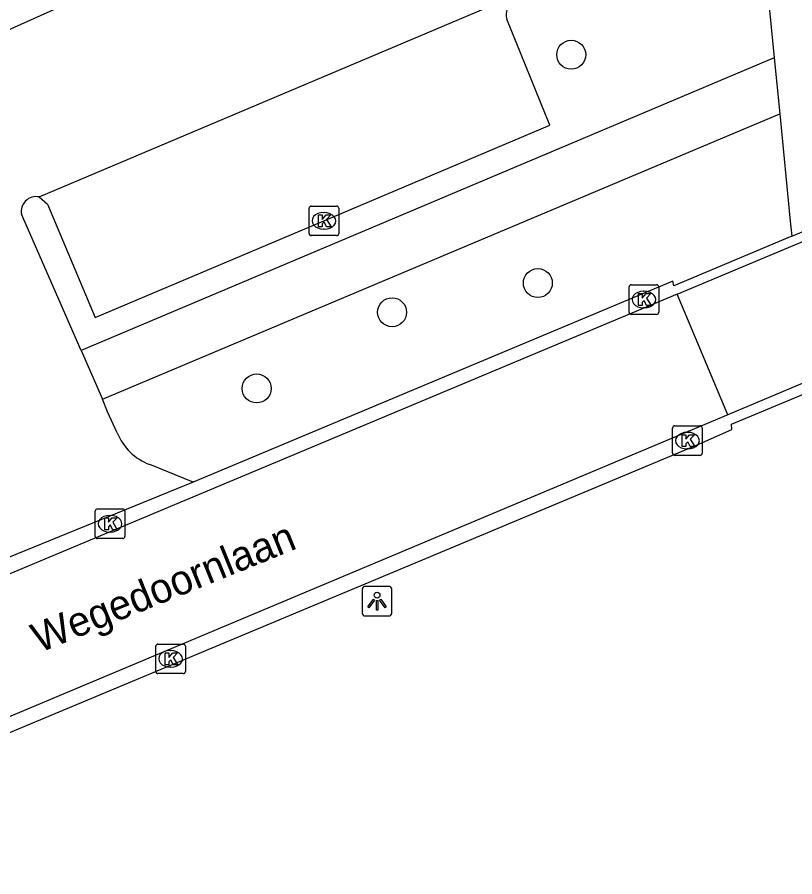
# Model space of a CAD drawing. Extents: x 162675 to 163482, y 379761 to 381227.
# Drawn here: x 163060.17 to 163086.44, y 380790.54 to 380819.57 of the extents above; entities that cross this region are included whole.
import ezdxf

# ---------------------------------------------------------------- set-up
doc = ezdxf.new("R2010")
doc.units = 0
for name, color, linetype in [('IMGEO_Boom', 7, 'Continuous'), ('IMGEO_Kolk', 7, 'Continuous'), ('IMGEO_Lichtpunt', 7, 'Continuous'), ('IMGEO_Openbare_ruimte_label', 7, 'Continuous'), ('IMGEO_Parkeervlak_open', 7, 'Continuous'), ('IMGEO_Rijbaan_lokaal_gesloten', 7, 'Continuous'), ('IMGEO_Rijbaan_lokaal_open', 7, 'Continuous'), ('IMGEO_Voetpad_open', 7, 'Continuous')]:
    doc.layers.add(name, color=color, linetype=linetype)

msp = doc.modelspace()

# ---------------------------------------------------------------- linework, layer by layer
at = {"layer": 'IMGEO_Boom'}
for centre in [(163078.885, 380818.302), (163077.757, 380810.591), (163072.834, 380809.603), (163068.26, 380807.03)]:
    msp.add_circle(centre, 0.489, dxfattribs=at)
at = {"layer": 'IMGEO_Kolk'}
for p, q in [((163070.105, 380813.191), (163070.957, 380813.191)), ((163070.03, 380812.265), (163070.03, 380813.117)), ((163070.518, 380812.971), (163070.543, 380812.971)), ((163071.031, 380813.117), (163071.031, 380812.265)), ((163070.541, 380812.411), (163070.516, 380812.411)), ((163070.957, 380812.191), (163070.105, 380812.191)), ((163080.839, 380809.607), (163080.839, 380810.459)), ((163080.914, 380810.533), (163081.766, 380810.533)), ((163081.327, 380810.313), (163081.352, 380810.313)), ((163081.84, 380810.459), (163081.84, 380809.607)), ((163081.35, 380809.753), (163081.325, 380809.753)), ((163081.766, 380809.533), (163080.914, 380809.533)), ((163082.31, 380804.842), (163082.31, 380805.694)), ((163082.385, 380805.768), (163083.237, 380805.768)), ((163083.311, 380805.694), (163083.311, 380804.842)), ((163082.798, 380805.548), (163082.823, 380805.548)), ((163082.821, 380804.988), (163082.796, 380804.988)), ((163083.237, 380804.768), (163082.385, 380804.768)), ((163062.808, 380802.033), (163062.808, 380802.885)), ((163062.883, 380802.959), (163063.735, 380802.959)), ((163063.296, 380802.739), (163063.321, 380802.739)), ((163063.809, 380802.885), (163063.809, 380802.033)), ((163063.319, 380802.179), (163063.294, 380802.179)), ((163063.735, 380801.959), (163062.883, 380801.959)), ((163064.925, 380798.397), (163065.777, 380798.397)), ((163064.85, 380797.471), (163064.85, 380798.323)), ((163065.338, 380798.177), (163065.363, 380798.177)), ((163065.851, 380798.323), (163065.851, 380797.471)), ((163065.361, 380797.617), (163065.336, 380797.617)), ((163065.777, 380797.397), (163064.925, 380797.397))]:
    msp.add_line(p, q, dxfattribs=at)
for points in [[(163070.105, 380813.191), (163070.957, 380813.191)], [(163070.03, 380812.265), (163070.03, 380813.117)], [(163071.031, 380813.117), (163071.031, 380812.265)], [(163070.351, 380812.891), (163070.474, 380812.891), (163070.474, 380812.74), (163070.604, 380812.891), (163070.768, 380812.891), (163070.622, 380812.74), (163070.775, 380812.491), (163070.623, 380812.491), (163070.538, 380812.655), (163070.474, 380812.588), (163070.474, 380812.491), (163070.351, 380812.491), (163070.351, 380812.891)], [(163070.957, 380812.191), (163070.105, 380812.191)], [(163080.839, 380809.607), (163080.839, 380810.459)], [(163080.914, 380810.533), (163081.766, 380810.533)], [(163081.84, 380810.459), (163081.84, 380809.607)], [(163081.16, 380810.233), (163081.283, 380810.233), (163081.283, 380810.082), (163081.413, 380810.233), (163081.577, 380810.233), (163081.431, 380810.082), (163081.584, 380809.833), (163081.432, 380809.833), (163081.347, 380809.997), (163081.283, 380809.93), (163081.283, 380809.833), (163081.16, 380809.833), (163081.16, 380810.233)], [(163081.766, 380809.533), (163080.914, 380809.533)], [(163082.31, 380804.842), (163082.31, 380805.694)], [(163082.385, 380805.768), (163083.237, 380805.768)], [(163083.311, 380805.694), (163083.311, 380804.842)], [(163082.631, 380805.468), (163082.754, 380805.468), (163082.754, 380805.317), (163082.884, 380805.468), (163083.048, 380805.468), (163082.902, 380805.317), (163083.055, 380805.068), (163082.903, 380805.068), (163082.818, 380805.232), (163082.754, 380805.165), (163082.754, 380805.068), (163082.631, 380805.068), (163082.631, 380805.468)], [(163083.237, 380804.768), (163082.385, 380804.768)], [(163062.808, 380802.033), (163062.808, 380802.885)], [(163062.883, 380802.959), (163063.735, 380802.959)], [(163063.809, 380802.885), (163063.809, 380802.033)], [(163063.129, 380802.659), (163063.252, 380802.659), (163063.252, 380802.508), (163063.382, 380802.659), (163063.546, 380802.659), (163063.4, 380802.508), (163063.553, 380802.259), (163063.401, 380802.259), (163063.316, 380802.423), (163063.252, 380802.356), (163063.252, 380802.259), (163063.129, 380802.259), (163063.129, 380802.659)], [(163063.735, 380801.959), (163062.883, 380801.959)], [(163064.925, 380798.397), (163065.777, 380798.397)], [(163064.85, 380797.471), (163064.85, 380798.323)], [(163065.171, 380798.097), (163065.294, 380798.097), (163065.294, 380797.946), (163065.424, 380798.097), (163065.588, 380798.097), (163065.442, 380797.946), (163065.595, 380797.697), (163065.443, 380797.697), (163065.358, 380797.861), (163065.294, 380797.794), (163065.294, 380797.697), (163065.171, 380797.697), (163065.171, 380798.097)], [(163065.851, 380798.323), (163065.851, 380797.471)], [(163065.777, 380797.397), (163064.925, 380797.397)]]:
    msp.add_lwpolyline(points, dxfattribs=at)
for centre, start, end in [((163070.107, 380813.115), 91.552, 178.448), ((163070.107, 380813.115), 91.552, 178.448), ((163070.955, 380813.115), 1.552, 88.448), ((163070.955, 380813.115), 1.552, 88.448), ((163070.107, 380812.267), 181.552, 268.448), ((163070.107, 380812.267), 181.552, 268.448), ((163070.955, 380812.267), 271.552, 358.448), ((163070.955, 380812.267), 271.552, 358.448), ((163080.916, 380810.457), 91.552, 178.448), ((163080.916, 380810.457), 91.552, 178.448), ((163081.764, 380810.457), 1.552, 88.448), ((163081.764, 380810.457), 1.552, 88.448), ((163080.916, 380809.609), 181.552, 268.448), ((163080.916, 380809.609), 181.552, 268.448), ((163081.764, 380809.609), 271.552, 358.448), ((163081.764, 380809.609), 271.552, 358.448), ((163082.387, 380805.692), 91.552, 178.448), ((163082.387, 380805.692), 91.552, 178.448), ((163083.235, 380805.692), 1.552, 88.448), ((163083.235, 380805.692), 1.552, 88.448), ((163082.387, 380804.844), 181.552, 268.448), ((163082.387, 380804.844), 181.552, 268.448), ((163083.235, 380804.844), 271.552, 358.448), ((163083.235, 380804.844), 271.552, 358.448), ((163062.885, 380802.883), 91.552, 178.448), ((163062.885, 380802.883), 91.552, 178.448), ((163063.733, 380802.883), 1.552, 88.448), ((163063.733, 380802.883), 1.552, 88.448), ((163062.885, 380802.035), 181.552, 268.448), ((163062.885, 380802.035), 181.552, 268.448), ((163063.733, 380802.035), 271.552, 358.448), ((163063.733, 380802.035), 271.552, 358.448), ((163064.927, 380798.321), 91.552, 178.448), ((163064.927, 380798.321), 91.552, 178.448), ((163065.775, 380798.321), 1.552, 88.448), ((163065.775, 380798.321), 1.552, 88.448), ((163064.927, 380797.473), 181.552, 268.448), ((163064.927, 380797.473), 181.552, 268.448), ((163065.775, 380797.473), 271.552, 358.448), ((163065.775, 380797.473), 271.552, 358.448)]:
    msp.add_arc(centre, 0.0765, start, end, dxfattribs=at)
for centre, major_axis, ratio, start_param, end_param in [((163070.517, 380812.691), (-0.387, 0.002), 0.722429, 4.712389, 7.853982), ((163070.542, 380812.691), (-0.39, 0.002), 0.717154, 1.570796, 4.712389), ((163081.326, 380810.033), (-0.387, 0.002), 0.722429, 4.712389, 7.853982), ((163081.351, 380810.033), (-0.39, 0.002), 0.717154, 1.570796, 4.712389), ((163082.797, 380805.268), (-0.387, 0.002), 0.722429, 4.712389, 7.853982), ((163082.822, 380805.268), (-0.39, 0.002), 0.717154, 1.570796, 4.712389), ((163063.295, 380802.459), (-0.387, 0.002), 0.722429, 4.712389, 7.853982), ((163063.32, 380802.459), (-0.39, 0.002), 0.717154, 1.570796, 4.712389), ((163065.337, 380797.897), (-0.387, 0.002), 0.722429, 4.712389, 7.853982), ((163065.362, 380797.897), (-0.39, 0.002), 0.717154, 1.570796, 4.712389)]:
    msp.add_ellipse(centre, major_axis=major_axis, ratio=ratio, start_param=start_param, end_param=end_param, dxfattribs=at)
at = {"layer": 'IMGEO_Lichtpunt'}
for p, q in [((163071.827, 380800.248), (163071.827, 380799.441)), ((163071.827, 380800.248), (163071.827, 380799.441)), ((163072.729, 380800.343), (163071.921, 380800.343)), ((163072.729, 380800.343), (163071.921, 380800.343)), ((163072.823, 380799.441), (163072.823, 380800.248)), ((163072.823, 380799.441), (163072.823, 380800.248)), ((163071.921, 380799.347), (163072.729, 380799.347)), ((163071.921, 380799.347), (163072.729, 380799.347))]:
    msp.add_line(p, q, dxfattribs=at)
for points in [[(163072.201, 380799.912), (163072.24, 380799.884), (163072.052, 380799.622), (163072.014, 380799.649), (163072.201, 380799.912)], [(163072.303, 380799.864), (163072.35, 380799.864), (163072.35, 380799.542), (163072.303, 380799.542), (163072.303, 380799.864)], [(163072.413, 380799.884), (163072.451, 380799.911), (163072.638, 380799.649), (163072.599, 380799.621), (163072.413, 380799.884)]]:
    msp.add_lwpolyline(points, dxfattribs=at)
msp.add_circle((163072.326, 380800.046), 0.0994, dxfattribs=at)
for centre, start, end in [((163071.921, 380800.248), 90, 180), ((163071.921, 380800.248), 90, 180), ((163072.729, 380800.248), 0, 90), ((163072.729, 380800.248), 0, 90), ((163071.921, 380799.441), 180, 270), ((163071.921, 380799.441), 180, 270), ((163072.729, 380799.441), 270, 0), ((163072.729, 380799.441), 270, 360)]:
    msp.add_arc(centre, 0.0946, start, end, dxfattribs=at)
at = {"layer": 'IMGEO_Parkeervlak_open'}
msp.add_lwpolyline([(163060.909, 380813.499), (163061.196, 380813.26), (163062.81, 380809.423), (163070.531, 380812.691), (163078.166, 380815.925), (163076.711, 380819.508)], dxfattribs=at)
msp.add_arc((163077.16, 380819.665), 0.475, 115.5108, 199.2772, dxfattribs=at)
at = {"layer": 'IMGEO_Rijbaan_lokaal_gesloten'}
for points in [[(163082.46, 380810.212), (163088.886, 380812.904), (163093.232, 380814.726)], [(163082.46, 380810.212), (163056.639, 380799.397), (163055.384, 380798.871)], [(163084.178, 380806.144), (163082.46, 380810.212)], [(163090.719, 380808.893), (163084.178, 380806.144)], [(163084.178, 380806.144), (163047.036, 380790.535)]]:
    msp.add_lwpolyline(points, dxfattribs=at)
at = {"layer": 'IMGEO_Rijbaan_lokaal_open'}
for points in [[(163060.909, 380813.499), (163076.492, 380820.088), (163069.295, 380841.425)], [(163062.677, 380820.399), (163058.226, 380818.404), (163051.902, 380832.986), (163048.567, 380840.674)], [(163062.33, 380808.317), (163060.316, 380812.916)], [(163086.334, 380812.174), (163088.324, 380813.011)], [(163086.334, 380812.174), (163082.346, 380810.499), (163082.321, 380810.658), (163066.12, 380803.87)], [(163062.33, 380808.317), (163063.051, 380806.669)], [(163048.473, 380790.555), (163050.701, 380791.564), (163068.745, 380799.107), (163083.113, 380805.114), (163084.311, 380805.649), (163084.294, 380805.828), (163086.729, 380806.834)], [(163063.551, 380805.527), (163063.217, 380806.239), (163063.051, 380806.669)], [(163066.12, 380803.87), (163064.648, 380804.462)], [(163066.12, 380803.87), (163057.298, 380800.27)]]:
    msp.add_lwpolyline(points, dxfattribs=at)
for centre, radius, start, end in [((163060.806, 380813.01), 0.499, 78.1564, 190.8692), ((163065.3, 380806.231), 1.885, 201.9255, 249.7704)]:
    msp.add_arc(centre, radius, start, end, dxfattribs=at)
at = {"layer": 'IMGEO_Voetpad_open'}
for points in [[(163080.608, 380856.801), (163082.925, 380846.97), (163085.744, 380818.198)], [(163085.744, 380818.198), (163062.33, 380808.317)], [(163085.744, 380818.198), (163085.929, 380816.31)], [(163063.051, 380806.669), (163085.929, 380816.31)], [(163085.929, 380816.31), (163086.284, 380812.685), (163086.334, 380812.174)]]:
    msp.add_lwpolyline(points, dxfattribs=at)

# ---------------------------------------------------------------- texts
at = {"layer": 'IMGEO_Openbare_ruimte_label'}
msp.add_text('Wegedoornlaan', height=1, rotation=22.0779, dxfattribs=at).set_placement((163060.916, 380798.088))

doc.saveas('drawing.dxf')
